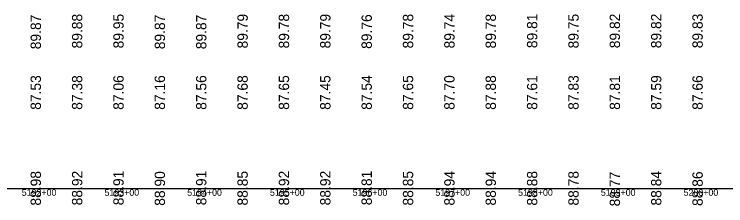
# Model space of a CAD drawing. Extents: x 2147288 to 2220488, y 740833 to 759333.
# Drawn here: x 2201548 to 2202408, y 750062 to 750294 of the extents above; entities that cross this region are included whole.
import ezdxf

# ---------------------------------------------------------------- set-up
doc = ezdxf.new("R2010")
doc.units = 0
for name, color, linetype in [('RD_DDB_Profile_EX', 7, 'Continuous'), ('RD_DDB_StaTX', 7, 'Continuous'), ('RD_DDB_StripGrade', 7, 'Continuous'), ('RD_GPK_Profile_Cell', 7, 'Continuous')]:
    doc.layers.add(name, color=color, linetype=linetype)

msp = doc.modelspace()

# ---------------------------------------------------------------- linework, layer by layer
at = {"layer": 'RD_GPK_Profile_Cell'}
msp.add_line((2198888.28, 750083.43), (2220488.28, 750083.43), dxfattribs=at)

# ---------------------------------------------------------------- texts
at = {"layer": 'RD_DDB_Profile_EX'}
for s, p in [('89.87', (2201580.08, 750251.67)), ('89.88', (2201630.08, 750252.64)), ('89.95', (2201680.08, 750252.69)), ('89.87', (2201730.08, 750251.67)), ('89.87', (2201780.08, 750251.67)), ('89.79', (2201830.08, 750252.64)), ('89.78', (2201880.08, 750252.64)), ('89.79', (2201930.08, 750252.64)), ('89.76', (2201980.08, 750252.13)), ('89.78', (2202030.08, 750252.64)), ('89.74', (2202080.08, 750252.66)), ('89.78', (2202130.08, 750252.64)), ('89.81', (2202180.08, 750253)), ('89.75', (2202230.08, 750252.69)), ('89.82', (2202280.08, 750252.89)), ('89.82', (2202330.08, 750252.89)), ('89.83', (2202380.08, 750252.89)), ('88.98', (2201580.08, 750062.64)), ('88.92', (2201630.08, 750062.89)), ('88.91', (2201680.08, 750063)), ('88.90', (2201730.08, 750062.38)), ('88.91', (2201780.08, 750063)), ('88.85', (2201830.08, 750062.69)), ('88.92', (2201880.08, 750062.89)), ('88.92', (2201930.08, 750062.89)), ('88.81', (2201980.08, 750063)), ('88.85', (2202030.08, 750062.69)), ('88.94', (2202080.08, 750062.66)), ('88.94', (2202130.08, 750062.66)), ('88.88', (2202180.08, 750062.64)), ('88.78', (2202230.08, 750062.64)), ('88.77', (2202280.08, 750061.67)), ('88.84', (2202330.08, 750062.66)), ('88.86', (2202380.08, 750062.13))]:
    msp.add_text(s, height=12.5, rotation=90, dxfattribs=at).set_placement(p)
at = {"layer": 'RD_DDB_StaTX'}
for s, p in [('5192+00', (2201556.88, 750074.43)), ('5192+00', (2201556.88, 750074.43)), ('5192+00', (2201556.88, 750074.43)), ('5193+00', (2201656.88, 750074.43)), ('5193+00', (2201656.88, 750074.43)), ('5193+00', (2201656.88, 750074.43)), ('5194+00', (2201756.88, 750074.43)), ('5194+00', (2201756.88, 750074.43)), ('5194+00', (2201756.88, 750074.43)), ('5195+00', (2201856.88, 750074.43)), ('5195+00', (2201856.88, 750074.43)), ('5195+00', (2201856.88, 750074.43)), ('5196+00', (2201956.88, 750074.43)), ('5196+00', (2201956.88, 750074.43)), ('5196+00', (2201956.88, 750074.43)), ('5197+00', (2202056.88, 750074.43)), ('5197+00', (2202056.88, 750074.43)), ('5197+00', (2202056.88, 750074.43)), ('5198+00', (2202156.88, 750074.43)), ('5198+00', (2202156.88, 750074.43)), ('5198+00', (2202156.88, 750074.43)), ('5199+00', (2202256.88, 750074.43)), ('5199+00', (2202256.88, 750074.43)), ('5199+00', (2202256.88, 750074.43)), ('5200+00', (2202356.88, 750074.43)), ('5200+00', (2202356.88, 750074.43)), ('5200+00', (2202356.88, 750074.43))]:
    msp.add_text(s, height=8, dxfattribs=at).set_placement(p)
at = {"layer": 'RD_DDB_StripGrade'}
for s, p in [('87.53', (2201580.08, 750178.43)), ('87.38', (2201630.08, 750178.43)), ('87.06', (2201680.08, 750178.43)), ('87.16', (2201730.08, 750178.43)), ('87.56', (2201780.08, 750178.43)), ('87.68', (2201830.08, 750178.43)), ('87.65', (2201880.08, 750178.43)), ('87.45', (2201930.08, 750178.43)), ('87.54', (2201980.08, 750178.43)), ('87.65', (2202030.08, 750178.43)), ('87.70', (2202080.08, 750178.43)), ('87.88', (2202130.08, 750178.43)), ('87.61', (2202180.08, 750178.43)), ('87.83', (2202230.08, 750178.43)), ('87.81', (2202280.08, 750178.43)), ('87.59', (2202330.08, 750178.43)), ('87.66', (2202380.08, 750178.43))]:
    msp.add_text(s, height=12.5, rotation=90, dxfattribs=at).set_placement(p)

doc.saveas('drawing.dxf')
